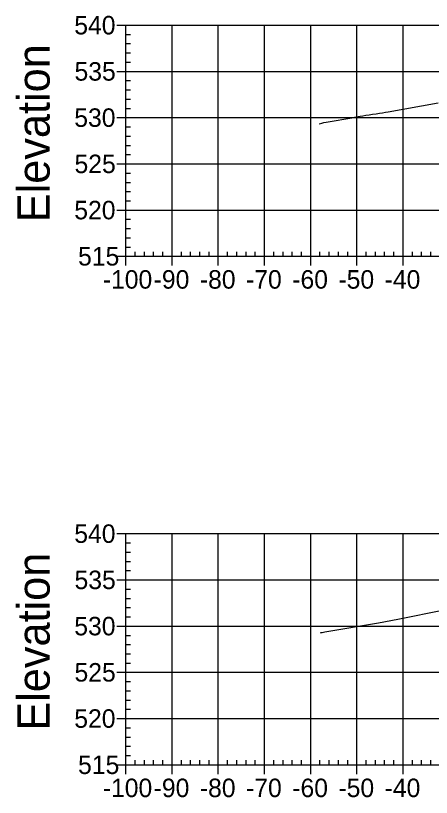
# Model space of a CAD drawing. Extents: x 708103 to 717568, y 374476 to 378707.
# Drawn here: x 716782.6 to 716872.6, y 376971 to 377140.1 of the extents above; entities that cross this region are included whole.
import ezdxf

# ---------------------------------------------------------------- set-up
doc = ezdxf.new("R2010")
doc.units = 0
for name, color, linetype in [('57', 7, 'Continuous'), ('60', 7, 'Continuous'), ('Existing', 7, 'Continuous')]:
    doc.layers.add(name, color=color, linetype=linetype)

msp = doc.modelspace()

# ---------------------------------------------------------------- linework, layer by layer
at = {"layer": '57'}
for p, q in [((716804.5, 377138.07), (716806.5, 377138.07)), ((716806.5, 377138.07), (717006.5, 377138.07)), ((716806.5, 377088.07), (716806.5, 377138.07)), ((716806.5, 377088.07), (716806.5, 377138.07)), ((716816.5, 377088.07), (716816.5, 377138.07)), ((716826.5, 377088.07), (716826.5, 377138.07)), ((716836.5, 377088.07), (716836.5, 377138.07)), ((716846.5, 377088.07), (716846.5, 377138.07)), ((716856.5, 377088.07), (716856.5, 377138.07)), ((716866.5, 377088.07), (716866.5, 377138.07)), ((716806.5, 377136.07), (716807.5, 377136.07)), ((716806.5, 377134.07), (716807.5, 377134.07)), ((716806.5, 377132.07), (716807.5, 377132.07)), ((716806.5, 377130.07), (716807.5, 377130.07)), ((716804.5, 377128.07), (716806.5, 377128.07)), ((716806.5, 377128.07), (717006.5, 377128.07)), ((716806.5, 377126.07), (716807.5, 377126.07)), ((716806.5, 377124.07), (716807.5, 377124.07)), ((716806.5, 377122.07), (716807.5, 377122.07)), ((716806.5, 377120.07), (716807.5, 377120.07)), ((716804.5, 377118.07), (716806.5, 377118.07)), ((716806.5, 377118.07), (717006.5, 377118.07)), ((716806.5, 377116.07), (716807.5, 377116.07)), ((716806.5, 377114.07), (716807.5, 377114.07)), ((716806.5, 377112.07), (716807.5, 377112.07)), ((716806.5, 377110.07), (716807.5, 377110.07)), ((716804.5, 377108.07), (716806.5, 377108.07)), ((716806.5, 377108.07), (717006.5, 377108.07)), ((716806.5, 377106.07), (716807.5, 377106.07)), ((716806.5, 377104.07), (716807.5, 377104.07)), ((716806.5, 377102.07), (716807.5, 377102.07)), ((716806.5, 377100.07), (716807.5, 377100.07)), ((716804.5, 377098.07), (716806.5, 377098.07)), ((716806.5, 377098.07), (717006.5, 377098.07)), ((716806.5, 377096.07), (716807.5, 377096.07)), ((716806.5, 377094.07), (716807.5, 377094.07)), ((716806.5, 377092.07), (716807.5, 377092.07)), ((716806.5, 377090.07), (716807.5, 377090.07)), ((716808.5, 377088.07), (716808.5, 377089.07)), ((716810.5, 377088.07), (716810.5, 377089.07)), ((716812.5, 377088.07), (716812.5, 377089.07)), ((716814.5, 377088.07), (716814.5, 377089.07)), ((716818.5, 377088.07), (716818.5, 377089.07)), ((716820.5, 377088.07), (716820.5, 377089.07)), ((716822.5, 377088.07), (716822.5, 377089.07)), ((716824.5, 377088.07), (716824.5, 377089.07)), ((716828.5, 377088.07), (716828.5, 377089.07)), ((716830.5, 377088.07), (716830.5, 377089.07)), ((716832.5, 377088.07), (716832.5, 377089.07)), ((716834.5, 377088.07), (716834.5, 377089.07)), ((716838.5, 377088.07), (716838.5, 377089.07)), ((716840.5, 377088.07), (716840.5, 377089.07)), ((716842.5, 377088.07), (716842.5, 377089.07)), ((716844.5, 377088.07), (716844.5, 377089.07)), ((716848.5, 377088.07), (716848.5, 377089.07)), ((716850.5, 377088.07), (716850.5, 377089.07)), ((716852.5, 377088.07), (716852.5, 377089.07)), ((716854.5, 377088.07), (716854.5, 377089.07)), ((716858.5, 377088.07), (716858.5, 377089.07)), ((716860.5, 377088.07), (716860.5, 377089.07)), ((716862.5, 377088.07), (716862.5, 377089.07)), ((716864.5, 377088.07), (716864.5, 377089.07)), ((716868.5, 377088.07), (716868.5, 377089.07)), ((716870.5, 377088.07), (716870.5, 377089.07)), ((716872.5, 377088.07), (716872.5, 377089.07)), ((716804.5, 377088.07), (716806.5, 377088.07)), ((716806.5, 377088.07), (717006.5, 377088.07)), ((716806.5, 377088.07), (717006.5, 377088.07)), ((716806.5, 377086.07), (716806.5, 377088.07)), ((716816.5, 377086.07), (716816.5, 377088.07)), ((716826.5, 377086.07), (716826.5, 377088.07)), ((716836.5, 377086.07), (716836.5, 377088.07)), ((716846.5, 377086.07), (716846.5, 377088.07)), ((716856.5, 377086.07), (716856.5, 377088.07)), ((716866.5, 377086.07), (716866.5, 377088.07)), ((716804.5, 377028.07), (716806.5, 377028.07)), ((716806.5, 377028.07), (717006.5, 377028.07)), ((716806.5, 376978.07), (716806.5, 377028.07)), ((716806.5, 376978.07), (716806.5, 377028.07)), ((716816.5, 376978.07), (716816.5, 377028.07)), ((716826.5, 376978.07), (716826.5, 377028.07)), ((716836.5, 376978.07), (716836.5, 377028.07)), ((716846.5, 376978.07), (716846.5, 377028.07)), ((716856.5, 376978.07), (716856.5, 377028.07)), ((716866.5, 376978.07), (716866.5, 377028.07)), ((716806.5, 377026.07), (716807.5, 377026.07)), ((716806.5, 377024.07), (716807.5, 377024.07)), ((716806.5, 377022.07), (716807.5, 377022.07)), ((716806.5, 377020.07), (716807.5, 377020.07)), ((716804.5, 377018.07), (716806.5, 377018.07)), ((716806.5, 377018.07), (717006.5, 377018.07)), ((716806.5, 377016.07), (716807.5, 377016.07)), ((716806.5, 377014.07), (716807.5, 377014.07)), ((716806.5, 377012.07), (716807.5, 377012.07)), ((716806.5, 377010.07), (716807.5, 377010.07)), ((716804.5, 377008.07), (716806.5, 377008.07)), ((716806.5, 377008.07), (717006.5, 377008.07)), ((716806.5, 377006.07), (716807.5, 377006.07)), ((716806.5, 377004.07), (716807.5, 377004.07)), ((716806.5, 377002.07), (716807.5, 377002.07)), ((716806.5, 377000.07), (716807.5, 377000.07)), ((716804.5, 376998.07), (716806.5, 376998.07)), ((716806.5, 376998.07), (717006.5, 376998.07)), ((716806.5, 376996.07), (716807.5, 376996.07)), ((716806.5, 376994.07), (716807.5, 376994.07)), ((716806.5, 376992.07), (716807.5, 376992.07)), ((716806.5, 376990.07), (716807.5, 376990.07)), ((716804.5, 376988.07), (716806.5, 376988.07)), ((716806.5, 376988.07), (717006.5, 376988.07)), ((716806.5, 376986.07), (716807.5, 376986.07)), ((716806.5, 376984.07), (716807.5, 376984.07)), ((716806.5, 376982.07), (716807.5, 376982.07)), ((716806.5, 376980.07), (716807.5, 376980.07)), ((716808.5, 376978.07), (716808.5, 376979.07)), ((716810.5, 376978.07), (716810.5, 376979.07)), ((716812.5, 376978.07), (716812.5, 376979.07)), ((716814.5, 376978.07), (716814.5, 376979.07)), ((716818.5, 376978.07), (716818.5, 376979.07)), ((716820.5, 376978.07), (716820.5, 376979.07)), ((716822.5, 376978.07), (716822.5, 376979.07)), ((716824.5, 376978.07), (716824.5, 376979.07)), ((716828.5, 376978.07), (716828.5, 376979.07)), ((716830.5, 376978.07), (716830.5, 376979.07)), ((716832.5, 376978.07), (716832.5, 376979.07)), ((716834.5, 376978.07), (716834.5, 376979.07)), ((716838.5, 376978.07), (716838.5, 376979.07)), ((716840.5, 376978.07), (716840.5, 376979.07)), ((716842.5, 376978.07), (716842.5, 376979.07)), ((716844.5, 376978.07), (716844.5, 376979.07)), ((716848.5, 376978.07), (716848.5, 376979.07)), ((716850.5, 376978.07), (716850.5, 376979.07)), ((716852.5, 376978.07), (716852.5, 376979.07)), ((716854.5, 376978.07), (716854.5, 376979.07)), ((716858.5, 376978.07), (716858.5, 376979.07)), ((716860.5, 376978.07), (716860.5, 376979.07)), ((716862.5, 376978.07), (716862.5, 376979.07)), ((716864.5, 376978.07), (716864.5, 376979.07)), ((716868.5, 376978.07), (716868.5, 376979.07)), ((716870.5, 376978.07), (716870.5, 376979.07)), ((716872.5, 376978.07), (716872.5, 376979.07)), ((716804.5, 376978.07), (716806.5, 376978.07)), ((716806.5, 376978.07), (717006.5, 376978.07)), ((716806.5, 376978.07), (717006.5, 376978.07)), ((716806.5, 376976.07), (716806.5, 376978.07)), ((716816.5, 376976.07), (716816.5, 376978.07)), ((716826.5, 376976.07), (716826.5, 376978.07)), ((716836.5, 376976.07), (716836.5, 376978.07)), ((716846.5, 376976.07), (716846.5, 376978.07)), ((716856.5, 376976.07), (716856.5, 376978.07)), ((716866.5, 376976.07), (716866.5, 376978.07))]:
    msp.add_line(p, q, dxfattribs=at)
at = {"layer": 'Existing'}
for points in [[(716848.36, 377116.73), (716848.59, 377116.81), (716848.91, 377116.9), (716849.32, 377117), (716849.83, 377117.12), (716855.85, 377118.12), (716856.04, 377118.17), (716856.35, 377118.23), (716856.74, 377118.3), (716857.23, 377118.38), (716857.81, 377118.47), (716858.46, 377118.57), (716859.16, 377118.68), (716859.9, 377118.79), (716860.66, 377118.91), (716861.41, 377119.03), (716862.07, 377119.14), (716862.69, 377119.25), (716863.25, 377119.34), (716874.12, 377121.24)], [(716848.58, 377006.6), (716848.74, 377006.65), (716848.95, 377006.71), (716849.23, 377006.78), (716849.57, 377006.86), (716861.18, 377008.8), (716865.35, 377009.54), (716875.38, 377011.57), (716894.28, 377015.33), (716902.06, 377015.75), (716908.28, 377016), (716918.44, 377016.23), (716923.93, 377015.25), (716937.42, 377012.9), (716959.13, 377008.21), (716964.96, 377006.89), (716966.39, 377006.19), (716985.86, 377004.37), (716986.56, 377004.39), (716987.02, 377004.4)]]:
    msp.add_lwpolyline(points, dxfattribs=at)

# ---------------------------------------------------------------- texts
at = {"layer": '57'}
for s, p in [('540', (716795.32, 377136.07)), ('535', (716795.37, 377126.07)), ('530', (716795.32, 377116.07)), ('525', (716795.37, 377106.07)), ('520', (716795.32, 377096.07)), ('515', (716796.14, 377086.07)), ('-100', (716801.49, 377081.07)), ('-90', (716812.5, 377081.07)), ('-80', (716822.5, 377081.07)), ('-70', (716832.5, 377081.07)), ('-60', (716842.5, 377081.07)), ('-50', (716852.5, 377081.07)), ('-40', (716862.5, 377081.07)), ('540', (716795.32, 377026.07)), ('535', (716795.37, 377016.07)), ('530', (716795.32, 377006.07)), ('525', (716795.37, 376996.07)), ('520', (716795.32, 376986.07)), ('515', (716796.14, 376976.07)), ('-100', (716801.49, 376971.07)), ('-90', (716812.5, 376971.07)), ('-80', (716822.5, 376971.07)), ('-70', (716832.5, 376971.07)), ('-60', (716842.5, 376971.07)), ('-50', (716852.5, 376971.07)), ('-40', (716862.5, 376971.07))]:
    msp.add_text(s, height=4, dxfattribs=at).set_placement(p)
at = {"layer": '60'}
for p in [(716790, 377095.44), (716790, 376985.44)]:
    msp.add_text('Elevation', height=7, rotation=90, dxfattribs=at).set_placement(p)

doc.saveas('drawing.dxf')
